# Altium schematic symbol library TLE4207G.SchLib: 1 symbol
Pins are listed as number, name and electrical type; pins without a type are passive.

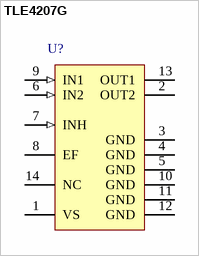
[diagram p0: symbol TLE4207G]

## TLE4207G
designator U?
1 A Dual-HBD (Dual-Half-Bridge Driver), -40 to 150 degC, PG-DSO-14-22, Reel, Green; Manufacturer: Infineon; PartNumber: TLE4207G; Green: TRUE; Group: Multi Half Bridges; IPeak: 2 x 1 A; Iq: 2 x 0.8 A; Iq (typ): 20 uA; Protect: short circuit e.a.
footprint INF-PG-DSO-14-22_N (SOP, 14-Leads, Body 8.65x3.9mm, Pitch 1.27mm, IPC Medium Density)
footprint INF-PG-DSO-14-22_L (SOP, 14-Leads, Body 8.65x3.9mm, Pitch 1.27mm, IPC High Density)
footprint INF-PG-DSO-14-22_M (SOP, 14-Leads, Body 8.65x3.9mm, Pitch 1.27mm, IPC Low Density)
pins: 1 VS (power) "Power supply voltage; positive reference potential for blocking capacitor", 2 OUT2 (power) "Power output 2; short circuit protected; with integrated clamp diodes", 3 GND (power) "Ground; negative reference potential for blocking capacitor", 4 GND (power) "Ground; negative reference potential for blocking capacitor", 5 GND (power) "Ground; negative reference potential for blocking capacitor", 6 IN2 (in) "Input channel 2; controls OUT2 (not inverted)", 7 INH (in) "Inhibit input; low = IC in stand-by", 8 EF (oc) "Error Flag output; open collector; low = error", 9 IN1 (in) "Input channel 1; controls OUT1 (not inverted)", 10 GND (power) "Ground; negative reference potential for blocking capacitor", 11 GND (power) "Ground; negative reference potential for blocking capacitor", 12 GND (power) "Ground; negative reference potential for blocking capacitor", 13 OUT1 (power) "Power output 1; short circuit protected; with integrated clamp diodes", 14 NC "Not connected"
